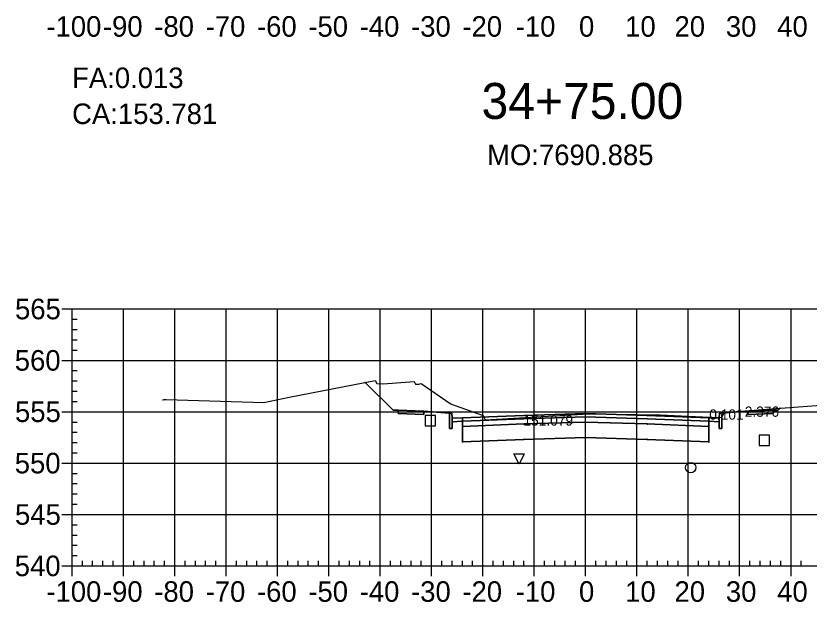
# Model space of a CAD drawing. Extents: x 704834 to 709892, y 372981 to 377533.
# Drawn here: x 707125.9 to 707280.4, y 373115.8 to 373229.9 of the extents above; entities that cross this region are included whole.
import ezdxf

# ---------------------------------------------------------------- set-up
doc = ezdxf.new("R2010")
doc.units = 0
for name, color, linetype in [('1', 7, 'Continuous'), ('10', 7, 'Continuous'), ('13', 7, 'Continuous'), ('14', 7, 'Continuous'), ('4', 7, 'Continuous'), ('57', 7, 'Continuous'), ('59', 7, 'Continuous'), ('Default_Xsect', 7, 'Continuous'), ('Existing', 7, 'Continuous')]:
    doc.layers.add(name, color=color, linetype=linetype)

msp = doc.modelspace()

# ---------------------------------------------------------------- linework, layer by layer
for points in [[(707199.37, 373153.11), (707193.95, 373158.54)], [(707274.37, 373153.11), (707274.76, 373153.5)], [(707200.37, 373153.15), (707199.37, 373153.11)], [(707210.37, 373152.55), (707205.37, 373152.95)], [(707263.37, 373152.55), (707268.37, 373152.95)], [(707273.37, 373153.15), (707274.37, 373153.11)]]:
    msp.add_lwpolyline(points)
for points in [[(707205.37, 373152.95), (707200.37, 373153.15), (707200.37, 373152.48), (707205.37, 373152.28)], [(707210.87, 373151.55), (707210.79, 373152.55), (707210.37, 373152.55), (707210.37, 373149.55), (707210.87, 373149.55)], [(707236.87, 373151.8), (707248.87, 373151.44), (707260.87, 373150.96), (707260.87, 373151.63), (707248.87, 373152.11), (707236.87, 373152.47), (707224.87, 373152.11), (707212.87, 373151.63), (707212.87, 373150.96), (707224.87, 373151.44)], [(707262.87, 373149.55), (707263.37, 373149.55), (707263.37, 373152.55), (707262.96, 373152.55), (707262.87, 373151.55)], [(707268.37, 373152.28), (707273.37, 373152.48), (707273.37, 373153.15), (707268.37, 373152.95)], [(707212.87, 373151.63), (707210.87, 373151.55), (707210.87, 373150.88), (707212.87, 373150.96)], [(707236.87, 373150.8), (707248.87, 373150.44), (707260.87, 373149.96), (707260.87, 373150.96), (707248.87, 373151.44), (707236.87, 373151.8), (707224.87, 373151.44), (707212.87, 373150.96), (707212.87, 373149.96), (707224.87, 373150.44)], [(707236.87, 373147.8), (707248.87, 373147.44), (707260.87, 373146.96), (707260.87, 373149.96), (707248.87, 373150.44), (707236.87, 373150.8), (707224.87, 373150.44), (707212.87, 373149.96), (707212.87, 373146.96), (707224.87, 373147.44)], [(707224.82, 373150.39), (707224.92, 373150.39), (707224.92, 373150.49), (707224.82, 373150.49)], [(707236.82, 373151.75), (707236.92, 373151.75), (707236.92, 373151.85), (707236.82, 373151.85)], [(707236.82, 373150.75), (707236.92, 373150.75), (707236.92, 373150.85), (707236.82, 373150.85)], [(707248.82, 373150.39), (707248.92, 373150.39), (707248.92, 373150.49), (707248.82, 373150.49)], [(707260.87, 373150.96), (707262.87, 373150.88), (707262.87, 373151.55), (707260.87, 373151.63)], [(707212.82, 373149.91), (707212.92, 373149.91), (707212.92, 373150.01), (707212.82, 373150.01)], [(707260.82, 373149.91), (707260.92, 373149.91), (707260.92, 373150.01), (707260.82, 373150.01)], [(707224.82, 373147.39), (707224.92, 373147.39), (707224.92, 373147.49), (707224.82, 373147.49)], [(707236.82, 373147.75), (707236.92, 373147.75), (707236.92, 373147.85), (707236.82, 373147.85)], [(707248.82, 373147.39), (707248.92, 373147.39), (707248.92, 373147.49), (707248.82, 373147.49)], [(707212.82, 373146.91), (707212.92, 373146.91), (707212.92, 373147.01), (707212.82, 373147.01)], [(707260.82, 373146.91), (707260.92, 373146.91), (707260.92, 373147.01), (707260.82, 373147.01)]]:
    msp.add_lwpolyline(points, close=True)
at = {"layer": '1'}
for points in [[(707193.95, 373158.54), (707195.88, 373158.92), (707196.19, 373158.29), (707197.43, 373158.26), (707203.45, 373158.71), (707203.75, 373158.19), (707204.42, 373158.21), (707204.82, 373158.33), (707210.52, 373154.43), (707210.56, 373154.4), (707210.59, 373154.39), (707216.91, 373152.1), (707217.1, 373151.65), (707217.3, 373151.23), (707237.43, 373152.39), (707237.68, 373152.4), (707237.9, 373152.4), (707251.36, 373152.19), (707259.66, 373151.84), (707263.37, 373151.72), (707263.37, 373149.55), (707262.87, 373149.55), (707262.87, 373150.88), (707260.87, 373150.96), (707260.87, 373149.96), (707260.87, 373146.96), (707248.87, 373147.44), (707236.87, 373147.8), (707224.87, 373147.44), (707212.87, 373146.96), (707212.87, 373149.96), (707212.87, 373150.96), (707210.87, 373150.88), (707210.87, 373149.55), (707210.37, 373149.55), (707210.37, 373152.55), (707205.37, 373152.95), (707205.37, 373152.28), (707200.37, 373152.48), (707200.37, 373153.15), (707199.37, 373153.11)], [(707263.88, 373152.59), (707266.21, 373152.86), (707274.76, 373153.5), (707274.37, 373153.11), (707273.37, 373153.15), (707273.37, 373152.48), (707268.37, 373152.28), (707268.37, 373152.95)], [(707263.37, 373151.72), (707263.39, 373151.72), (707263.44, 373151.84), (707263.86, 373152.59), (707263.37, 373152.55)], [(707223.91, 373142.61), (707222.91, 373144.61), (707224.91, 373144.61)]]:
    msp.add_lwpolyline(points, close=True, dxfattribs=at)
at = {"layer": '10'}
msp.add_lwpolyline([(707205.65, 373150.07), (707207.65, 373150.07), (707207.65, 373152.07), (707205.65, 373152.07)], close=True, dxfattribs=at)
at = {"layer": '13'}
msp.add_circle((707257.34, 373141.94), 1, dxfattribs=at)
at = {"layer": '14'}
for points in [[(707193.95, 373158.54), (707193.95, 373158.59), (707193.95, 373158.54), (707193.9, 373158.54), (707193.95, 373158.54), (707193.95, 373158.49), (707193.95, 373158.54), (707194, 373158.54)], [(707274.76, 373153.5), (707274.76, 373153.55), (707274.76, 373153.5), (707274.71, 373153.5), (707274.76, 373153.5), (707274.76, 373153.45), (707274.76, 373153.5), (707274.81, 373153.5)], [(707224.87, 373152.11), (707224.87, 373152.16), (707224.87, 373152.11), (707224.82, 373152.11), (707224.87, 373152.11), (707224.87, 373152.06), (707224.87, 373152.11), (707224.92, 373152.11)], [(707236.87, 373152.47), (707236.87, 373152.52), (707236.87, 373152.47), (707236.82, 373152.47), (707236.87, 373152.47), (707236.87, 373152.42), (707236.87, 373152.47), (707236.92, 373152.47)], [(707248.87, 373152.11), (707248.87, 373152.16), (707248.87, 373152.11), (707248.82, 373152.11), (707248.87, 373152.11), (707248.87, 373152.06), (707248.87, 373152.11), (707248.92, 373152.11)], [(707212.87, 373151.63), (707212.87, 373151.68), (707212.87, 373151.63), (707212.82, 373151.63), (707212.87, 373151.63), (707212.87, 373151.58), (707212.87, 373151.63), (707212.92, 373151.63)], [(707260.87, 373151.63), (707260.87, 373151.68), (707260.87, 373151.63), (707260.82, 373151.63), (707260.87, 373151.63), (707260.87, 373151.58), (707260.87, 373151.63), (707260.92, 373151.63)]]:
    msp.add_lwpolyline(points, dxfattribs=at)
at = {"layer": '4'}
msp.add_lwpolyline([(707270.68, 373146.27), (707272.68, 373146.27), (707272.68, 373148.27), (707270.68, 373148.27)], close=True, dxfattribs=at)
at = {"layer": '57'}
for p, q in [((707134.87, 373172.82), (707136.87, 373172.82)), ((707136.87, 373172.82), (707336.87, 373172.82)), ((707136.87, 373122.82), (707136.87, 373172.82)), ((707136.87, 373122.82), (707136.87, 373172.82)), ((707146.87, 373122.82), (707146.87, 373172.82)), ((707156.87, 373122.82), (707156.87, 373172.82)), ((707166.87, 373122.82), (707166.87, 373172.82)), ((707176.87, 373122.82), (707176.87, 373172.82)), ((707186.87, 373122.82), (707186.87, 373172.82)), ((707196.87, 373122.82), (707196.87, 373172.82)), ((707206.87, 373122.82), (707206.87, 373172.82)), ((707216.87, 373122.82), (707216.87, 373172.82)), ((707226.87, 373122.82), (707226.87, 373172.82)), ((707236.87, 373122.82), (707236.87, 373172.82)), ((707246.87, 373122.82), (707246.87, 373172.82)), ((707256.87, 373122.82), (707256.87, 373172.82)), ((707266.87, 373122.82), (707266.87, 373172.82)), ((707276.87, 373122.82), (707276.87, 373172.82)), ((707136.87, 373170.82), (707137.87, 373170.82)), ((707136.87, 373168.82), (707137.87, 373168.82)), ((707136.87, 373166.82), (707137.87, 373166.82)), ((707136.87, 373164.82), (707137.87, 373164.82)), ((707134.87, 373162.82), (707136.87, 373162.82)), ((707136.87, 373162.82), (707336.87, 373162.82)), ((707136.87, 373160.82), (707137.87, 373160.82)), ((707136.87, 373158.82), (707137.87, 373158.82)), ((707136.87, 373156.82), (707137.87, 373156.82)), ((707136.87, 373154.82), (707137.87, 373154.82)), ((707134.87, 373152.82), (707136.87, 373152.82)), ((707136.87, 373152.82), (707336.87, 373152.82)), ((707136.87, 373150.82), (707137.87, 373150.82)), ((707136.87, 373148.82), (707137.87, 373148.82)), ((707136.87, 373146.82), (707137.87, 373146.82)), ((707136.87, 373144.82), (707137.87, 373144.82)), ((707134.87, 373142.82), (707136.87, 373142.82)), ((707136.87, 373142.82), (707336.87, 373142.82)), ((707136.87, 373140.82), (707137.87, 373140.82)), ((707136.87, 373138.82), (707137.87, 373138.82)), ((707136.87, 373136.82), (707137.87, 373136.82)), ((707136.87, 373134.82), (707137.87, 373134.82)), ((707134.87, 373132.82), (707136.87, 373132.82)), ((707136.87, 373132.82), (707336.87, 373132.82)), ((707136.87, 373130.82), (707137.87, 373130.82)), ((707136.87, 373128.82), (707137.87, 373128.82)), ((707136.87, 373126.82), (707137.87, 373126.82)), ((707136.87, 373124.82), (707137.87, 373124.82)), ((707134.87, 373122.82), (707136.87, 373122.82)), ((707136.87, 373122.82), (707336.87, 373122.82)), ((707136.87, 373122.82), (707336.87, 373122.82)), ((707136.87, 373120.82), (707136.87, 373122.82)), ((707138.87, 373122.82), (707138.87, 373123.82)), ((707140.87, 373122.82), (707140.87, 373123.82)), ((707142.87, 373122.82), (707142.87, 373123.82)), ((707144.87, 373122.82), (707144.87, 373123.82)), ((707146.87, 373120.82), (707146.87, 373122.82)), ((707148.87, 373122.82), (707148.87, 373123.82)), ((707150.87, 373122.82), (707150.87, 373123.82)), ((707152.87, 373122.82), (707152.87, 373123.82)), ((707154.87, 373122.82), (707154.87, 373123.82)), ((707156.87, 373120.82), (707156.87, 373122.82)), ((707158.87, 373122.82), (707158.87, 373123.82)), ((707160.87, 373122.82), (707160.87, 373123.82)), ((707162.87, 373122.82), (707162.87, 373123.82)), ((707164.87, 373122.82), (707164.87, 373123.82)), ((707166.87, 373120.82), (707166.87, 373122.82)), ((707168.87, 373122.82), (707168.87, 373123.82)), ((707170.87, 373122.82), (707170.87, 373123.82)), ((707172.87, 373122.82), (707172.87, 373123.82)), ((707174.87, 373122.82), (707174.87, 373123.82)), ((707176.87, 373120.82), (707176.87, 373122.82)), ((707178.87, 373122.82), (707178.87, 373123.82)), ((707180.87, 373122.82), (707180.87, 373123.82)), ((707182.87, 373122.82), (707182.87, 373123.82)), ((707184.87, 373122.82), (707184.87, 373123.82)), ((707186.87, 373120.82), (707186.87, 373122.82)), ((707188.87, 373122.82), (707188.87, 373123.82)), ((707190.87, 373122.82), (707190.87, 373123.82)), ((707192.87, 373122.82), (707192.87, 373123.82)), ((707194.87, 373122.82), (707194.87, 373123.82)), ((707196.87, 373120.82), (707196.87, 373122.82)), ((707198.87, 373122.82), (707198.87, 373123.82)), ((707200.87, 373122.82), (707200.87, 373123.82)), ((707202.87, 373122.82), (707202.87, 373123.82)), ((707204.87, 373122.82), (707204.87, 373123.82)), ((707206.87, 373120.82), (707206.87, 373122.82)), ((707208.87, 373122.82), (707208.87, 373123.82)), ((707210.87, 373122.82), (707210.87, 373123.82)), ((707212.87, 373122.82), (707212.87, 373123.82)), ((707214.87, 373122.82), (707214.87, 373123.82)), ((707216.87, 373120.82), (707216.87, 373122.82)), ((707218.87, 373122.82), (707218.87, 373123.82)), ((707220.87, 373122.82), (707220.87, 373123.82)), ((707222.87, 373122.82), (707222.87, 373123.82)), ((707224.87, 373122.82), (707224.87, 373123.82)), ((707226.87, 373120.82), (707226.87, 373122.82)), ((707228.87, 373122.82), (707228.87, 373123.82)), ((707230.87, 373122.82), (707230.87, 373123.82)), ((707232.87, 373122.82), (707232.87, 373123.82)), ((707234.87, 373122.82), (707234.87, 373123.82)), ((707236.87, 373120.82), (707236.87, 373122.82)), ((707238.87, 373122.82), (707238.87, 373123.82)), ((707240.87, 373122.82), (707240.87, 373123.82)), ((707242.87, 373122.82), (707242.87, 373123.82)), ((707244.87, 373122.82), (707244.87, 373123.82)), ((707246.87, 373120.82), (707246.87, 373122.82)), ((707248.87, 373122.82), (707248.87, 373123.82)), ((707250.87, 373122.82), (707250.87, 373123.82)), ((707252.87, 373122.82), (707252.87, 373123.82)), ((707254.87, 373122.82), (707254.87, 373123.82)), ((707256.87, 373120.82), (707256.87, 373122.82)), ((707258.87, 373122.82), (707258.87, 373123.82)), ((707260.87, 373122.82), (707260.87, 373123.82)), ((707262.87, 373122.82), (707262.87, 373123.82)), ((707264.87, 373122.82), (707264.87, 373123.82)), ((707266.87, 373120.82), (707266.87, 373122.82)), ((707268.87, 373122.82), (707268.87, 373123.82)), ((707270.87, 373122.82), (707270.87, 373123.82)), ((707272.87, 373122.82), (707272.87, 373123.82)), ((707274.87, 373122.82), (707274.87, 373123.82)), ((707276.87, 373120.82), (707276.87, 373122.82)), ((707278.87, 373122.82), (707278.87, 373123.82))]:
    msp.add_line(p, q, dxfattribs=at)
at = {"layer": 'Default_Xsect'}
msp.add_lwpolyline([(707193.95, 373158.54), (707199.37, 373153.11), (707200.37, 373153.15), (707205.37, 373152.95), (707210.37, 373152.55), (707210.79, 373152.55), (707210.87, 373151.55), (707212.87, 373151.63), (707224.87, 373152.11), (707236.87, 373152.47), (707248.87, 373152.11), (707260.87, 373151.63), (707262.87, 373151.55), (707262.96, 373152.55), (707263.37, 373152.55), (707268.37, 373152.95), (707273.37, 373153.15), (707274.37, 373153.11), (707274.76, 373153.5)], dxfattribs=at)
at = {"layer": 'Existing'}
msp.add_lwpolyline([(707154.48, 373155.16), (707154.59, 373155.13), (707154.77, 373155.22), (707155.18, 373155.18), (707174.23, 373154.64), (707179.17, 373155.64), (707195.88, 373158.92), (707196.19, 373158.29), (707197.43, 373158.26), (707203.45, 373158.71), (707203.75, 373158.19), (707204.42, 373158.21), (707204.82, 373158.33), (707210.52, 373154.43), (707210.56, 373154.4), (707210.59, 373154.39), (707216.91, 373152.1), (707217.1, 373151.65), (707217.3, 373151.23), (707237.43, 373152.39), (707237.68, 373152.4), (707237.9, 373152.4), (707251.36, 373152.19), (707259.66, 373151.84), (707263.39, 373151.72), (707263.44, 373151.84), (707263.86, 373152.59), (707266.21, 373152.86), (707284.45, 373154.21)], dxfattribs=at)

# ---------------------------------------------------------------- texts
msp.add_text('CA:153.781', height=4).set_placement((707136.87, 373208.82))
at = {"layer": '1'}
msp.add_text('34+75.00', height=7, dxfattribs=at).set_placement((707216.6, 373209.82))
at = {"layer": '14'}
for p in [(707200.34, 373153.1), (707200.34, 373152.43), (707205.34, 373152.23), (707268.34, 373152.23), (707273.34, 373153.1), (707273.34, 373152.43)]:
    msp.add_text('+', height=0.1, dxfattribs=at).set_placement(p)
at = {"layer": '57'}
for s, p in [('-100', (707131.86, 373225.82)), ('-90', (707142.87, 373225.82)), ('-80', (707152.87, 373225.82)), ('-70', (707162.87, 373225.82)), ('-60', (707172.87, 373225.82)), ('-50', (707182.87, 373225.82)), ('-40', (707192.87, 373225.82)), ('-30', (707202.87, 373225.82)), ('-20', (707212.87, 373225.82)), ('-10', (707223.26, 373225.82)), ('0', (707235.58, 373225.82)), ('10', (707244.57, 373225.82)), ('20', (707254.18, 373225.82)), ('30', (707264.18, 373225.82)), ('40', (707274.18, 373225.82)), ('565', (707125.75, 373170.82)), ('560', (707125.7, 373160.82)), ('555', (707125.75, 373150.82)), ('550', (707125.7, 373140.82)), ('545', (707125.75, 373130.82)), ('540', (707125.7, 373120.82)), ('-100', (707131.86, 373115.82)), ('-90', (707142.87, 373115.82)), ('-80', (707152.87, 373115.82)), ('-70', (707162.87, 373115.82)), ('-60', (707172.87, 373115.82)), ('-50', (707182.87, 373115.82)), ('-40', (707192.87, 373115.82)), ('-30', (707202.87, 373115.82)), ('-20', (707212.87, 373115.82)), ('-10', (707223.26, 373115.82)), ('0', (707235.58, 373115.82)), ('10', (707244.57, 373115.82)), ('20', (707254.18, 373115.82)), ('30', (707264.18, 373115.82)), ('40', (707274.18, 373115.82))]:
    msp.add_text(s, height=4, dxfattribs=at).set_placement(p)
at = {"layer": '59'}
for s, height, p in [('FA:0.013', 4, (707136.87, 373215.82)), ('MO:7690.885', 4, (707217.68, 373200.82)), ('2.376', 2, (707267.86, 373151.84)), ('151.079', 2, (707224.76, 373150.12)), ('0.101', 2, (707260.95, 373151.28))]:
    msp.add_text(s, height=height, dxfattribs=at).set_placement(p)

doc.saveas('drawing.dxf')
